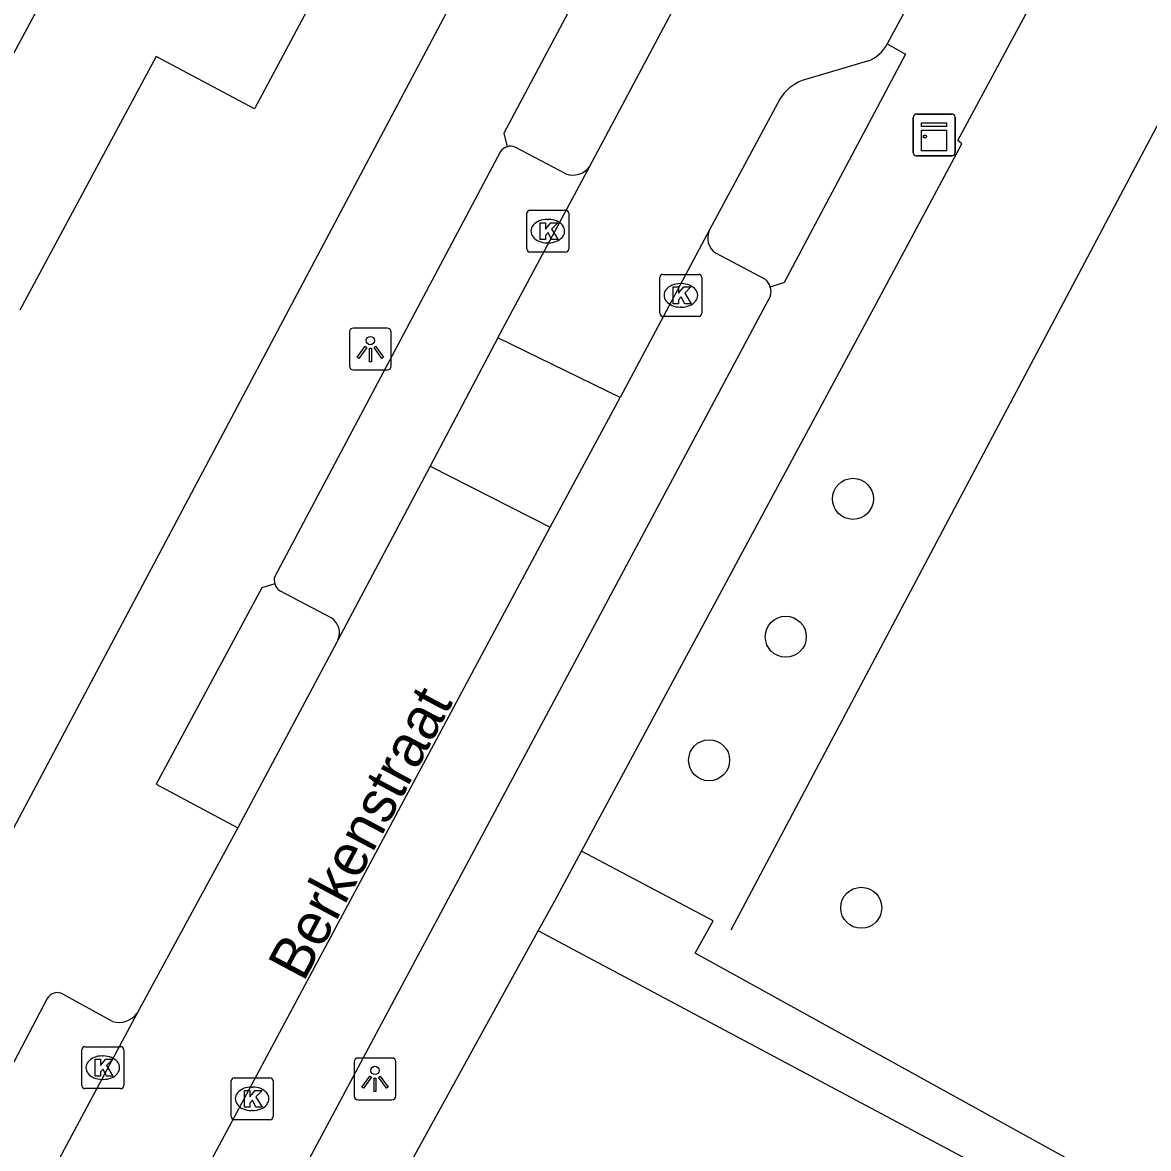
# Model space of a CAD drawing. Extents: x 159265 to 160143, y 383413 to 384319.
# Drawn here: x 159904.97 to 159931.8, y 383789.75 to 383816.59 of the extents above; entities that cross this region are included whole.
import ezdxf

# ---------------------------------------------------------------- set-up
doc = ezdxf.new("R2010")
doc.units = 0
for name, color, linetype in [('IMGEO_Boom', 7, 'Continuous'), ('IMGEO_Hek', 7, 'Continuous'), ('IMGEO_Kast', 7, 'Continuous'), ('IMGEO_Kolk', 7, 'Continuous'), ('IMGEO_Lichtpunt', 7, 'Continuous'), ('IMGEO_Openbare_ruimte_label', 7, 'Continuous'), ('IMGEO_Pand', 7, 'Continuous'), ('IMGEO_Parkeervlak_open', 7, 'Continuous'), ('IMGEO_Rijbaan_lokaal_open', 7, 'Continuous'), ('IMGEO_Voetpad_open', 7, 'Continuous')]:
    doc.layers.add(name, color=color, linetype=linetype)

msp = doc.modelspace()

# ---------------------------------------------------------------- linework, layer by layer
at = {"layer": 'IMGEO_Boom'}
for centre in [(159924.757, 383805.236), (159923.156, 383801.949), (159921.329, 383799.004), (159924.954, 383795.489)]:
    msp.add_circle(centre, 0.489, dxfattribs=at)
at = {"layer": 'IMGEO_Hek'}
for points in [[(159932.975, 383815.963), (159928.778, 383808.042)], [(159928.778, 383808.042), (159921.843, 383794.954)]]:
    msp.add_lwpolyline(points, dxfattribs=at)
at = {"layer": 'IMGEO_Kast'}
for p, q in [((159926.193, 383813.484), (159926.193, 383814.325)), ((159926.193, 383814.325), (159926.193, 383813.484)), ((159926.268, 383814.409), (159927.109, 383814.409)), ((159927.109, 383814.409), (159926.268, 383814.409)), ((159927.193, 383814.334), (159927.193, 383813.493)), ((159927.193, 383813.493), (159927.193, 383814.334)), ((159927.118, 383813.409), (159926.277, 383813.409)), ((159926.277, 383813.409), (159927.118, 383813.409))]:
    msp.add_line(p, q, dxfattribs=at)
for points in [[(159926.388, 383814.199), (159926.988, 383814.199), (159926.988, 383814.114), (159926.388, 383814.114), (159926.388, 383814.199)], [(159926.388, 383814.024), (159926.988, 383814.024), (159926.988, 383813.535), (159926.388, 383813.535), (159926.388, 383814.024)]]:
    msp.add_lwpolyline(points, dxfattribs=at)
msp.add_circle((159926.472, 383813.873), 0.0377, dxfattribs=at)
for centre, start, end in [((159926.271, 383814.331), 92.4484, 184.2845), ((159926.271, 383814.331), 92.4484, 184.2845), ((159927.115, 383814.331), 2.4484, 94.2845), ((159927.115, 383814.331), 2.4484, 94.2845), ((159926.271, 383813.487), 182.4484, 274.2845), ((159926.271, 383813.487), 182.4484, 274.2845), ((159927.115, 383813.487), 272.4484, 4.2845), ((159927.115, 383813.487), 272.4484, 4.2845)]:
    msp.add_arc(centre, 0.0779, start, end, dxfattribs=at)
at = {"layer": 'IMGEO_Kolk'}
for p, q in [((159916.983, 383811.192), (159916.983, 383812.044)), ((159917.058, 383812.118), (159917.91, 383812.118)), ((159917.471, 383811.898), (159917.496, 383811.898)), ((159917.984, 383812.044), (159917.984, 383811.192)), ((159917.494, 383811.338), (159917.469, 383811.338)), ((159917.91, 383811.118), (159917.058, 383811.118)), ((159920.23, 383810.586), (159921.082, 383810.586)), ((159920.155, 383809.66), (159920.155, 383810.512)), ((159920.643, 383810.366), (159920.668, 383810.366)), ((159921.156, 383810.512), (159921.156, 383809.66)), ((159920.666, 383809.806), (159920.641, 383809.806)), ((159921.082, 383809.586), (159920.23, 383809.586)), ((159906.377, 383791.252), (159906.377, 383792.104)), ((159906.452, 383792.178), (159907.304, 383792.178)), ((159907.378, 383792.104), (159907.378, 383791.252)), ((159906.865, 383791.958), (159906.89, 383791.958)), ((159906.888, 383791.398), (159906.863, 383791.398)), ((159909.936, 383790.51), (159909.936, 383791.362)), ((159910.011, 383791.436), (159910.863, 383791.436)), ((159910.424, 383791.216), (159910.449, 383791.216)), ((159910.937, 383791.362), (159910.937, 383790.51)), ((159907.304, 383791.178), (159906.452, 383791.178)), ((159910.863, 383790.436), (159910.011, 383790.436)), ((159910.447, 383790.656), (159910.422, 383790.656))]:
    msp.add_line(p, q, dxfattribs=at)
for points in [[(159916.983, 383811.192), (159916.983, 383812.044)], [(159917.058, 383812.118), (159917.91, 383812.118)], [(159917.984, 383812.044), (159917.984, 383811.192)], [(159917.304, 383811.818), (159917.427, 383811.818), (159917.427, 383811.667), (159917.557, 383811.818), (159917.721, 383811.818), (159917.575, 383811.667), (159917.728, 383811.418), (159917.576, 383811.418), (159917.491, 383811.582), (159917.427, 383811.515), (159917.427, 383811.418), (159917.304, 383811.418), (159917.304, 383811.818)], [(159917.91, 383811.118), (159917.058, 383811.118)], [(159920.23, 383810.586), (159921.082, 383810.586)], [(159920.155, 383809.66), (159920.155, 383810.512)], [(159920.476, 383810.286), (159920.599, 383810.286), (159920.599, 383810.135), (159920.729, 383810.286), (159920.893, 383810.286), (159920.747, 383810.135), (159920.9, 383809.886), (159920.748, 383809.886), (159920.663, 383810.05), (159920.599, 383809.983), (159920.599, 383809.886), (159920.476, 383809.886), (159920.476, 383810.286)], [(159921.156, 383810.512), (159921.156, 383809.66)], [(159921.082, 383809.586), (159920.23, 383809.586)], [(159906.377, 383791.252), (159906.377, 383792.104)], [(159906.452, 383792.178), (159907.304, 383792.178)], [(159907.378, 383792.104), (159907.378, 383791.252)], [(159906.698, 383791.878), (159906.821, 383791.878), (159906.821, 383791.727), (159906.951, 383791.878), (159907.115, 383791.878), (159906.969, 383791.727), (159907.122, 383791.478), (159906.97, 383791.478), (159906.885, 383791.642), (159906.821, 383791.575), (159906.821, 383791.478), (159906.698, 383791.478), (159906.698, 383791.878)], [(159909.936, 383790.51), (159909.936, 383791.362)], [(159910.011, 383791.436), (159910.863, 383791.436)], [(159910.937, 383791.362), (159910.937, 383790.51)], [(159907.304, 383791.178), (159906.452, 383791.178)], [(159910.257, 383791.136), (159910.38, 383791.136), (159910.38, 383790.985), (159910.51, 383791.136), (159910.674, 383791.136), (159910.528, 383790.985), (159910.681, 383790.736), (159910.529, 383790.736), (159910.444, 383790.9), (159910.38, 383790.833), (159910.38, 383790.736), (159910.257, 383790.736), (159910.257, 383791.136)], [(159910.863, 383790.436), (159910.011, 383790.436)]]:
    msp.add_lwpolyline(points, dxfattribs=at)
for centre, start, end in [((159917.06, 383812.042), 91.552, 178.448), ((159917.06, 383812.042), 91.552, 178.448), ((159917.908, 383812.042), 1.552, 88.448), ((159917.908, 383812.042), 1.552, 88.448), ((159917.06, 383811.194), 181.552, 268.448), ((159917.06, 383811.194), 181.552, 268.448), ((159917.908, 383811.194), 271.552, 358.448), ((159917.908, 383811.194), 271.552, 358.448), ((159920.232, 383810.51), 91.552, 178.448), ((159920.232, 383810.51), 91.552, 178.448), ((159921.08, 383810.51), 1.552, 88.448), ((159921.08, 383810.51), 1.552, 88.448), ((159920.232, 383809.662), 181.552, 268.448), ((159920.232, 383809.662), 181.552, 268.448), ((159921.08, 383809.662), 271.552, 358.448), ((159921.08, 383809.662), 271.552, 358.448), ((159906.454, 383792.102), 91.552, 178.448), ((159906.454, 383792.102), 91.552, 178.448), ((159907.302, 383792.102), 1.552, 88.448), ((159907.302, 383792.102), 1.552, 88.448), ((159906.454, 383791.254), 181.552, 268.448), ((159906.454, 383791.254), 181.552, 268.448), ((159907.302, 383791.254), 271.552, 358.448), ((159907.302, 383791.254), 271.552, 358.448), ((159910.013, 383791.36), 91.552, 178.448), ((159910.013, 383791.36), 91.552, 178.448), ((159910.861, 383791.36), 1.552, 88.448), ((159910.861, 383791.36), 1.552, 88.448), ((159910.013, 383790.512), 181.552, 268.448), ((159910.013, 383790.512), 181.552, 268.448), ((159910.861, 383790.512), 271.552, 358.448), ((159910.861, 383790.512), 271.552, 358.448)]:
    msp.add_arc(centre, 0.0765, start, end, dxfattribs=at)
for centre, major_axis, ratio, start_param, end_param in [((159917.47, 383811.618), (-0.387, 0.002), 0.722429, 4.712389, 7.853982), ((159917.495, 383811.618), (-0.39, 0.002), 0.717154, 1.570796, 4.712389), ((159920.642, 383810.086), (-0.387, 0.002), 0.722429, 4.712389, 7.853982), ((159920.667, 383810.086), (-0.39, 0.002), 0.717154, 1.570796, 4.712389), ((159906.864, 383791.678), (-0.387, 0.002), 0.722429, 4.712389, 7.853982), ((159906.889, 383791.678), (-0.39, 0.002), 0.717154, 1.570796, 4.712389), ((159910.423, 383790.936), (-0.387, 0.002), 0.722429, 4.712389, 7.853982), ((159910.448, 383790.936), (-0.39, 0.002), 0.717154, 1.570796, 4.712389)]:
    msp.add_ellipse(centre, major_axis=major_axis, ratio=ratio, start_param=start_param, end_param=end_param, dxfattribs=at)
at = {"layer": 'IMGEO_Lichtpunt'}
for p, q in [((159912.757, 383809.211), (159912.757, 383808.404)), ((159912.757, 383809.211), (159912.757, 383808.404)), ((159913.659, 383809.306), (159912.851, 383809.306)), ((159913.659, 383809.306), (159912.851, 383809.306)), ((159913.753, 383808.404), (159913.753, 383809.211)), ((159913.753, 383808.404), (159913.753, 383809.211)), ((159912.851, 383808.31), (159913.659, 383808.31)), ((159912.851, 383808.31), (159913.659, 383808.31)), ((159912.867, 383791.813), (159912.867, 383791.006)), ((159912.867, 383791.813), (159912.867, 383791.006)), ((159913.769, 383791.908), (159912.961, 383791.908)), ((159913.769, 383791.908), (159912.961, 383791.908)), ((159913.863, 383791.006), (159913.863, 383791.813)), ((159913.863, 383791.006), (159913.863, 383791.813)), ((159912.961, 383790.912), (159913.769, 383790.912)), ((159912.961, 383790.912), (159913.769, 383790.912))]:
    msp.add_line(p, q, dxfattribs=at)
for points in [[(159913.131, 383808.875), (159913.17, 383808.847), (159912.982, 383808.585), (159912.944, 383808.612), (159913.131, 383808.875)], [(159913.233, 383808.827), (159913.28, 383808.827), (159913.28, 383808.505), (159913.233, 383808.505), (159913.233, 383808.827)], [(159913.343, 383808.847), (159913.381, 383808.874), (159913.568, 383808.612), (159913.529, 383808.584), (159913.343, 383808.847)], [(159913.241, 383791.477), (159913.28, 383791.449), (159913.092, 383791.187), (159913.054, 383791.214), (159913.241, 383791.477)], [(159913.453, 383791.449), (159913.491, 383791.476), (159913.678, 383791.214), (159913.639, 383791.186), (159913.453, 383791.449)], [(159913.343, 383791.429), (159913.39, 383791.429), (159913.39, 383791.107), (159913.343, 383791.107), (159913.343, 383791.429)]]:
    msp.add_lwpolyline(points, dxfattribs=at)
for centre in [(159913.256, 383809.009), (159913.366, 383791.611)]:
    msp.add_circle(centre, 0.0994, dxfattribs=at)
for centre, start, end in [((159912.851, 383809.211), 90, 180), ((159912.851, 383809.211), 90, 180), ((159913.659, 383809.211), 0, 90), ((159913.659, 383809.211), 0, 90), ((159912.851, 383808.404), 180, 270), ((159912.851, 383808.404), 180, 270), ((159913.659, 383808.404), 270, 0), ((159913.659, 383808.404), 270, 360), ((159912.961, 383791.813), 90, 180), ((159912.961, 383791.813), 90, 180), ((159913.769, 383791.813), 0, 90), ((159913.769, 383791.813), 0, 90), ((159912.961, 383791.006), 180, 270), ((159912.961, 383791.006), 180, 270), ((159913.769, 383791.006), 270, 0), ((159913.769, 383791.006), 270, 360)]:
    msp.add_arc(centre, 0.0946, start, end, dxfattribs=at)
at = {"layer": 'IMGEO_Pand'}
for points in [[(159909.479, 383824.639), (159902.225, 383811.174)], [(159914.461, 383821.96), (159910.498, 383814.534), (159908.155, 383815.782), (159904.902, 383809.733)]]:
    msp.add_lwpolyline(points, dxfattribs=at)
at = {"layer": 'IMGEO_Parkeervlak_open'}
for points in [[(159917.913, 383812.979), (159916.703, 383813.622)], [(159922.674, 383810.461), (159921.493, 383811.089)], [(159911.087, 383803.053), (159912.328, 383802.396)]]:
    msp.add_lwpolyline(points, dxfattribs=at)
for centre, radius, start, end in [((159916.596, 383813.352), 0.29, 68.4525, 106.7255), ((159918.073, 383813.473), 0.519, 251.9962, 320.9918), ((159921.725, 383811.452), 0.431, 152.6824, 237.4473), ((159922.398, 383810.16), 0.408, 17.6561, 47.4537), ((159911.272, 383803.297), 0.307, 196.3691, 232.8324), ((159912.094, 383802.042), 0.425, 335.7451, 56.5173)]:
    msp.add_arc(centre, radius, start, end, dxfattribs=at)
at = {"layer": 'IMGEO_Rijbaan_lokaal_open'}
for points in [[(159926.828, 383818.404), (159925.576, 383816.083)], [(159918.477, 383813.146), (159920.767, 383817.458)], [(159925.128, 383815.679), (159923.55, 383815.211)], [(159923.014, 383814.764), (159921.342, 383811.65)], [(159916.294, 383809.074), (159918.477, 383813.146)], [(159921.342, 383811.65), (159919.212, 383807.655)], [(159916.294, 383809.074), (159914.678, 383806.016)], [(159919.212, 383807.655), (159916.294, 383809.074)], [(159917.54, 383804.561), (159919.212, 383807.655)], [(159914.678, 383806.016), (159912.481, 383801.867)], [(159914.678, 383806.016), (159917.54, 383804.561)], [(159908.14, 383787.005), (159917.54, 383804.561)], [(159912.481, 383801.867), (159912.456, 383801.82), (159910.095, 383797.392)], [(159910.095, 383797.392), (159907.699, 383792.974)], [(159907.699, 383792.974), (159904.455, 383786.925)]]:
    msp.add_lwpolyline(points, dxfattribs=at)
for centre, radius, start, end in [((159924.82, 383816.471), 0.85, 291.2624, 332.825), ((159923.971, 383814.162), 1.13, 111.8425, 147.8107)]:
    msp.add_arc(centre, radius, start, end, dxfattribs=at)
at = {"layer": 'IMGEO_Voetpad_open'}
for points in [[(159904.335, 383796.618), (159917.055, 383820.574)], [(159921.075, 383818.384), (159919.299, 383819.325), (159916.438, 383813.949), (159916.513, 383813.63)], [(159918.288, 383796.839), (159925.318, 383809.9), (159927.355, 383813.697), (159927.253, 383813.776), (159929.096, 383817.206)], [(159925.576, 383816.083), (159926.013, 383815.836), (159923.116, 383810.395), (159922.787, 383810.284)], [(159916.356, 383813.518), (159910.976, 383803.387)], [(159922.795, 383810.075), (159910.257, 383786.623)], [(159910.978, 383803.211), (159910.673, 383803.116), (159908.15, 383798.439), (159910.095, 383797.392)], [(159917.255, 383794.936), (159917.651, 383795.656), (159918.288, 383796.839)], [(159959.658, 383751.286), (159947.801, 383772.899), (159939.84, 383784), (159920.998, 383794.406), (159921.424, 383795.176), (159918.288, 383796.839)], [(159910.672, 383782.967), (159917.255, 383794.936)], [(159952.563, 383761.994), (159946.703, 383772.634), (159944.381, 383776.132), (159939.048, 383783.321), (159917.255, 383794.936)], [(159907.11, 383792.778), (159905.929, 383793.43)], [(159905.556, 383793.324), (159903.022, 383788.501)]]:
    msp.add_lwpolyline(points, dxfattribs=at)
for centre, radius, start, end in [((159916.598, 383813.345), 0.297, 106.545, 144.4613), ((159922.408, 383810.165), 0.397, 346.9324, 17.4517), ((159911.268, 383803.302), 0.304, 163.8464, 197.4557), ((159905.793, 383793.199), 0.268, 59.5948, 152.1336), ((159907.26, 383793.309), 0.552, 254.2139, 322.5976)]:
    msp.add_arc(centre, radius, start, end, dxfattribs=at)

# ---------------------------------------------------------------- texts
at = {"layer": 'IMGEO_Openbare_ruimte_label'}
msp.add_text('Berkenstraat', height=1, rotation=61.9477, dxfattribs=at).set_placement((159911.663, 383793.698))

doc.saveas('drawing.dxf')
